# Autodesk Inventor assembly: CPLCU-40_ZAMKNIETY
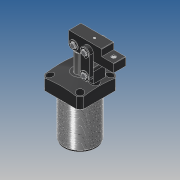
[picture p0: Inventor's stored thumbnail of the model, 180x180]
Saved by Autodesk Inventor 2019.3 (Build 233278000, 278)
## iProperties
Created: 2010-03
Part Number: CPLCU-40_ZAMKNIETY
Material: Ogólny
Document SubType Name: Assembly
Designer: CADENGINEERING4
Sending System: PRO/ENGINEER BY PARAMETRIC TECHNOLOGY CORPORATION, 2007170
Preprocessor: PRO/ENGINEER BY PARAMETRIC TECHNOLOGY CORPORATION, 2007170
Title: CPLCU-40_ASM
Author: Administrator
Revision Number: 2LAST_VERSION
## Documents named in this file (10)
- E:\SERWER_ZAPAS\MODELE brakujace\PNEUMATIC\CPLCU(STEP)\cplcu-40_asm\CPLCU-40_ZAMKNIETY.iam
- E:\SERWER_ZAPAS\MODELE brakujace\PNEUMATIC\CPLCU(STEP)\cplcu-40_asm\CPLCU-40-07.ipt
- E:\SERWER_ZAPAS\MODELE brakujace\PNEUMATIC\CPLCU(STEP)\cplcu-40_asm\CPLCU-40-05.ipt
- E:\SERWER_ZAPAS\MODELE brakujace\PNEUMATIC\CPLCU(STEP)\cplcu-40_asm\CPLCU-40-06.ipt
- E:\SERWER_ZAPAS\MODELE brakujace\PNEUMATIC\CPLCU(STEP)\cplcu-40_asm\CPLCU-40-01.ipt
- E:\SERWER_ZAPAS\MODELE brakujace\PNEUMATIC\CPLCU(STEP)\cplcu-40_asm\CPLCU-40-02.ipt
- E:\SERWER_ZAPAS\MODELE brakujace\PNEUMATIC\CPLCU(STEP)\cplcu-40_asm\CPLCU-40-08.ipt
- E:\SERWER_ZAPAS\MODELE brakujace\PNEUMATIC\CPLCU(STEP)\cplcu-40_asm\CPLCU-40-03.ipt
- E:\SERWER_ZAPAS\MODELE brakujace\PNEUMATIC\CPLCU(STEP)\cplcu-40_asm\CPLCU-40-04.ipt
- E:\SERWER_ZAPAS\MODELE brakujace\PNEUMATIC\CPLCU(STEP)\cplcu-40_asm\LHC01D-40-08.ipt
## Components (21 placed, 21 different names)
1. CPLCU-40-07_0 — Zestawiające:25
2. CPLCU-40-05_1 — Zestawiające:1, Zestawiające:2, Kątowe:1
3. CPLCU-40-06_2 — Zestawiające:15, Równoległe:4, Zestawiające:20, Zestawiające:21, Zestawiające:25
4. CPLCU-40-01_3 — Zestawiające:13, Zestawiające:14, Zestawiające:24, Kątowe:1
5. CPLCU-40-02_4 — Zestawiające:2, Zestawiające:3, Zestawiające:4
6. CPLCU-40-02_5 — Zestawiające:1, Zestawiające:3, Zestawiające:4, Zestawiające:5, Zestawiające:12, Zestawiające:14
7. CPLCU-40-08_6 — Zestawiające:17, Zestawiające:19, Zestawiające:21, Zestawiające:23
8. CPLCU-40-08_7 — Zestawiające:7, Zestawiające:11
9. CPLCU-40-08_8
10. CPLCU-40-08_9 — Zestawiające:16, Zestawiające:20, Zestawiające:22, Zestawiające:24
11. CPLCU-40-08_10 — Zestawiające:5
12. CPLCU-40-08_11 — Zestawiające:8, Zestawiające:9
13. CPLCU-40-03_12 — Zestawiające:15, Zestawiające:16, Zestawiające:17, Zestawiające:18, Równoległe:4
14. CPLCU-40-04_13 — Równoległe:1, Zestawiające:6, Zestawiające:7, Zestawiające:8, Zestawiające:10, Zestawiające:12, Zestawiające:13
15. CPLCU-40-04_14 — Równoległe:1
16. LHC01D-40-08_15 — Zestawiające:19, Zestawiające:23
17. LHC01D-40-08_16 — Zestawiające:18, Zestawiające:22
18. LHC01D-40-08_17 — Równoległe:3, Zestawiające:10, Zestawiające:11
19. LHC01D-40-08_18 — Równoległe:3
20. LHC01D-40-08_19 — Równoległe:2, Zestawiające:6, Zestawiające:9
21. LHC01D-40-08_20 — Równoległe:2
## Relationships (30: Mate 25, Flush 4, Angle 1)
- Równoległe:1 [Flush]: CPLCU-40-04_13 ↔ CPLCU-40-04_14
- Równoległe:2 [Flush]: LHC01D-40-08_19 ↔ LHC01D-40-08_20
- Równoległe:3 [Flush]: LHC01D-40-08_17 ↔ LHC01D-40-08_18
- Zestawiające:1 [Mate]: CPLCU-40-05_1 ↔ CPLCU-40-02_5
- Zestawiające:2 [Mate]: CPLCU-40-05_1 ↔ CPLCU-40-02_4
- Zestawiające:3 [Mate]: CPLCU-40-02_4 ↔ CPLCU-40-02_5
- Zestawiające:4 [Mate]: CPLCU-40-02_4 ↔ CPLCU-40-02_5
- Zestawiające:5 [Mate]: CPLCU-40-02_5 ↔ CPLCU-40-08_10
- Zestawiające:6 [Mate]: CPLCU-40-04_13 ↔ LHC01D-40-08_19
- Zestawiające:7 [Mate]: CPLCU-40-08_7 ↔ CPLCU-40-04_13
- Zestawiające:8 [Mate]: CPLCU-40-08_11 ↔ CPLCU-40-04_13
- Zestawiające:9 [Mate]: CPLCU-40-08_11 ↔ LHC01D-40-08_19
- Zestawiające:10 [Mate]: CPLCU-40-04_13 ↔ LHC01D-40-08_17
- Zestawiające:11 [Mate]: CPLCU-40-08_7 ↔ LHC01D-40-08_17
- Zestawiające:12 [Mate]: CPLCU-40-02_5 ↔ CPLCU-40-04_13
- Zestawiające:13 [Mate]: CPLCU-40-01_3 ↔ CPLCU-40-04_13
- Zestawiające:14 [Mate]: CPLCU-40-01_3 ↔ CPLCU-40-02_5
- Zestawiające:15 [Mate]: CPLCU-40-06_2 ↔ CPLCU-40-03_12
- Zestawiające:16 [Mate]: CPLCU-40-08_9 ↔ CPLCU-40-03_12
- Zestawiające:17 [Mate]: CPLCU-40-08_6 ↔ CPLCU-40-03_12
- Zestawiające:18 [Mate]: CPLCU-40-03_12 ↔ LHC01D-40-08_16
- Zestawiające:19 [Mate]: CPLCU-40-08_6 ↔ LHC01D-40-08_15
- Równoległe:4 [Flush]: CPLCU-40-06_2 ↔ CPLCU-40-03_12
- Zestawiające:20 [Mate]: CPLCU-40-06_2 ↔ CPLCU-40-08_9
- Zestawiające:21 [Mate]: CPLCU-40-06_2 ↔ CPLCU-40-08_6
- Zestawiające:22 [Mate]: CPLCU-40-08_9 ↔ LHC01D-40-08_16
- Zestawiające:23 [Mate]: CPLCU-40-08_6 ↔ LHC01D-40-08_15
- Zestawiające:24 [Mate]: CPLCU-40-01_3 ↔ CPLCU-40-08_9
- Zestawiające:25 [Mate]: CPLCU-40-07_0 ↔ CPLCU-40-06_2
- Kątowe:1 [Angle]: CPLCU-40-05_1 ↔ CPLCU-40-01_3
